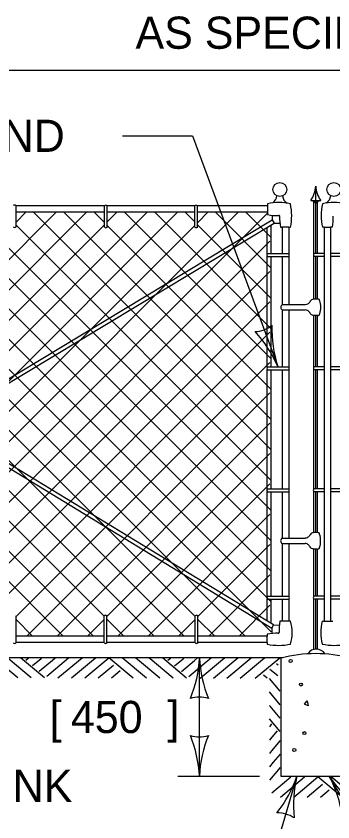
# Model space of a CAD drawing. Extents: x 49973.1 to 50021, y 49987.6 to 50015.4.
# Drawn here: x 49978.181 to 49978.772, y 50011.283 to 50012.786 of the extents above; entities that cross this region are included whole.
import ezdxf

# ---------------------------------------------------------------- set-up
doc = ezdxf.new("R2010")
doc.units = 0
for name, color, linetype in [('Level 1', 7, 'Continuous'), ('Level 2', 7, 'Continuous'), ('Level 3', 7, 'Continuous')]:
    doc.layers.add(name, color=color, linetype=linetype)

msp = doc.modelspace()

# ---------------------------------------------------------------- linework, layer by layer
at = {"layer": 'Level 1'}
for p, q in [((49978.7401, 50012.3432), (49978.7401, 50012.4689)), ((49978.6502, 50012.4358), (49978.6502, 50012.4319)), ((49978.7308, 50012.4423), (49978.7494, 50012.4423)), ((49978.7366, 50012.3431), (49978.7366, 50012.4399)), ((49978.7436, 50012.3432), (49978.7436, 50012.4396)), ((49977.5022, 50011.6663), (49978.256, 50012.4202)), ((49977.5222, 50011.6298), (49978.3126, 50012.4202)), ((49977.5348, 50012.4202), (49978.3255, 50011.6298)), ((49977.5914, 50012.4202), (49978.3451, 50011.6668)), ((49977.6718, 50011.6664), (49978.4256, 50012.4202)), ((49977.6918, 50011.6298), (49978.4822, 50012.4202)), ((49977.7044, 50012.4202), (49978.4946, 50011.6298)), ((49977.7609, 50012.4202), (49978.5149, 50011.6664)), ((49977.8416, 50011.6665), (49978.5954, 50012.4202)), ((49977.8742, 50012.4202), (49978.6567, 50011.638)), ((49977.9307, 50012.4202), (49978.6567, 50011.6939)), ((49978.044, 50012.4202), (49978.6567, 50011.8072)), ((49978.1004, 50012.4202), (49978.6567, 50011.8637)), ((49978.3456, 50012.4322), (49978.181, 50012.4322)), ((49978.1812, 50012.393), (49978.1812, 50012.4327)), ((49978.1812, 50012.402), (49978.1994, 50012.4202)), ((49978.3458, 50012.4202), (49978.1813, 50012.4202)), ((49978.2136, 50012.4202), (49978.6567, 50011.9769)), ((49978.2702, 50012.4202), (49978.6567, 50012.0335)), ((49978.3268, 50012.4202), (49978.3457, 50012.4013)), ((49978.3457, 50012.3925), (49978.3457, 50012.4322)), ((49978.5142, 50012.4322), (49978.351, 50012.4322)), ((49978.3512, 50012.3925), (49978.3512, 50012.4322)), ((49978.3512, 50012.4024), (49978.369, 50012.4202)), ((49978.5144, 50012.4202), (49978.3513, 50012.4202)), ((49978.3834, 50012.4202), (49978.6567, 50012.1467)), ((49978.4398, 50012.4202), (49978.6567, 50012.2031)), ((49978.4964, 50012.4202), (49978.5143, 50012.4024)), ((49978.5143, 50012.3927), (49978.5143, 50012.4324)), ((49978.5198, 50012.3927), (49978.5198, 50012.4324)), ((49978.65, 50012.4202), (49978.5198, 50012.4202)), ((49978.6502, 50012.4322), (49978.5199, 50012.4322)), ((49978.5199, 50012.4013), (49978.5388, 50012.4202)), ((49978.553, 50012.4202), (49978.6567, 50012.3163)), ((49978.6096, 50012.4202), (49978.6567, 50012.373)), ((49978.6502, 50012.4319), (49978.6502, 50012.4199)), ((49978.6502, 50012.4199), (49978.6502, 50012.416)), ((49977.3965, 50011.6456), (49978.6588, 50012.4061)), ((49978.6581, 50011.6442), (49977.4024, 50012.4082)), ((49978.6612, 50011.6505), (49977.4109, 50012.4113)), ((49977.8616, 50011.6298), (49978.6496, 50012.4178)), ((49978.6588, 50012.4147), (49978.6588, 50012.4061)), ((49978.6588, 50012.4061), (49978.6626, 50012.4002)), ((49977.4003, 50011.6397), (49978.6626, 50012.4002)), ((49977.5015, 50012.3969), (49978.269, 50011.6298)), ((49977.5786, 50011.6298), (49978.3457, 50012.3969)), ((49977.6718, 50012.3965), (49978.4388, 50011.6298)), ((49977.7484, 50011.6298), (49978.5143, 50012.3957)), ((49977.8416, 50012.3962), (49978.6083, 50011.6298)), ((49978.0112, 50012.3963), (49978.6567, 50011.7508)), ((49978.1812, 50012.396), (49978.6567, 50011.9202)), ((49978.3512, 50012.3958), (49978.6567, 50012.09)), ((49978.5198, 50012.3968), (49978.6567, 50012.2596)), ((49978.6497, 50012.3429), (49978.6497, 50012.3925)), ((49978.6567, 50012.3432), (49978.6567, 50012.3967)), ((49978.6626, 50012.4002), (49978.6733, 50012.4)), ((49978.6745, 50012.3923), (49978.6778, 50012.3923)), ((49978.6898, 50012.3923), (49978.6778, 50012.3923)), ((49978.6778, 50012.3923), (49978.6778, 50012.3432)), ((49978.6898, 50012.3923), (49978.693, 50012.3923)), ((49978.6898, 50012.3923), (49978.6898, 50012.3431)), ((49978.7557, 50012.3923), (49978.7525, 50012.3923)), ((49978.7557, 50012.3923), (49978.7677, 50012.3923)), ((49978.7557, 50012.3923), (49978.7557, 50012.3429)), ((49978.771, 50012.3923), (49978.7677, 50012.3923)), ((49978.7677, 50012.3923), (49978.7677, 50012.3432)), ((49977.918, 50011.6298), (49978.6544, 50012.3662)), ((49978.65, 50012.3432), (49978.6897, 50012.3432)), ((49978.7557, 50012.3432), (49978.7368, 50012.3432)), ((49978.7677, 50012.3432), (49978.7677, 50012.1318)), ((49978.7956, 50012.3432), (49978.7677, 50012.3432)), ((49978.6497, 50012.1314), (49978.6497, 50012.3381)), ((49978.65, 50012.3377), (49978.6897, 50012.3377)), ((49978.6567, 50012.1319), (49978.6567, 50012.3377)), ((49978.6778, 50012.3377), (49978.6778, 50012.248)), ((49978.6898, 50012.3379), (49978.6898, 50012.248)), ((49978.7366, 50012.2584), (49978.7366, 50012.338)), ((49978.7557, 50012.3377), (49978.7367, 50012.3377)), ((49978.7401, 50012.2584), (49978.7401, 50012.3377)), ((49978.7436, 50012.2584), (49978.7436, 50012.3377)), ((49978.7557, 50012.3429), (49978.7557, 50012.1319)), ((49978.7955, 50012.3377), (49978.7677, 50012.3377)), ((49978.0112, 50011.6665), (49978.6544, 50012.3096)), ((49978.0312, 50011.6298), (49978.6544, 50012.253)), ((49978.7436, 50012.2584), (49978.7367, 50012.2584)), ((49978.6778, 50012.248), (49978.7206, 50012.248)), ((49978.6778, 50012.238), (49978.7206, 50012.238)), ((49978.6778, 50012.238), (49978.6778, 50012.1319)), ((49978.6898, 50012.238), (49978.6898, 50012.1319)), ((49978.7366, 50012.1318), (49978.7366, 50012.2276)), ((49978.7438, 50012.2276), (49978.7367, 50012.2276)), ((49978.7401, 50012.1319), (49978.7401, 50012.2276)), ((49978.7436, 50012.1319), (49978.7436, 50012.2276)), ((49978.0878, 50011.6298), (49978.6544, 50012.1964)), ((49978.181, 50011.6664), (49978.6544, 50012.1398)), ((49978.6497, 50011.9041), (49978.6497, 50012.1269)), ((49978.6501, 50012.1264), (49978.6898, 50012.1264)), ((49978.6502, 50012.1319), (49978.6898, 50012.1319)), ((49978.6567, 50011.9044), (49978.6567, 50012.1264)), ((49978.6778, 50012.1264), (49978.6778, 50011.9044)), ((49978.6898, 50012.1264), (49978.6898, 50011.9043)), ((49978.7366, 50011.9044), (49978.7366, 50012.1266)), ((49978.7557, 50012.1264), (49978.7367, 50012.1264)), ((49978.7557, 50012.1319), (49978.7368, 50012.1319)), ((49978.7401, 50011.9044), (49978.7401, 50012.1264)), ((49978.7436, 50011.9044), (49978.7436, 50012.1264)), ((49978.7557, 50012.1319), (49978.7557, 50011.904)), ((49978.7954, 50012.1319), (49978.7677, 50012.1319)), ((49978.7677, 50012.1318), (49978.7677, 50011.8988)), ((49978.7954, 50012.1264), (49978.7677, 50012.1264)), ((49978.201, 50011.6298), (49978.6544, 50012.0832)), ((49978.2576, 50011.6298), (49978.6544, 50012.0266)), ((49978.3506, 50011.6664), (49978.6544, 50011.9702)), ((49978.3706, 50011.6298), (49978.6544, 50011.9136)), ((49978.6497, 50011.7034), (49978.6497, 50011.8993)), ((49978.65, 50011.9044), (49978.6897, 50011.9044)), ((49978.65, 50011.8989), (49978.6897, 50011.8989)), ((49978.6567, 50011.704), (49978.6567, 50011.8989)), ((49978.6778, 50011.8989), (49978.6778, 50011.8124)), ((49978.6898, 50011.8991), (49978.6898, 50011.8124)), ((49978.7557, 50011.8989), (49978.7365, 50011.8989)), ((49978.7557, 50011.9044), (49978.7366, 50011.9044)), ((49978.7366, 50011.8228), (49978.7366, 50011.8989)), ((49978.7401, 50011.8228), (49978.7401, 50011.8989)), ((49978.7436, 50011.8229), (49978.7436, 50011.8989)), ((49978.7557, 50011.904), (49978.7557, 50011.7039)), ((49978.7956, 50011.9044), (49978.7677, 50011.9044)), ((49978.7955, 50011.8989), (49978.7677, 50011.8989)), ((49978.7677, 50011.8988), (49978.7677, 50011.704)), ((49978.4272, 50011.6298), (49978.6544, 50011.857)), ((49978.7433, 50011.8228), (49978.7364, 50011.8228)), ((49978.6775, 50011.8024), (49978.7203, 50011.8024)), ((49978.6776, 50011.8124), (49978.7203, 50011.8124)), ((49978.6778, 50011.8024), (49978.6778, 50011.704)), ((49978.6898, 50011.8024), (49978.6898, 50011.704)), ((49978.5204, 50011.6663), (49978.6544, 50011.8004)), ((49978.7435, 50011.792), (49978.7364, 50011.792)), ((49978.7366, 50011.704), (49978.7366, 50011.792)), ((49978.7401, 50011.704), (49978.7401, 50011.792)), ((49978.7436, 50011.704), (49978.7436, 50011.792)), ((49978.5404, 50011.6298), (49978.6544, 50011.7438)), ((49978.6497, 50011.6575), (49978.6497, 50011.6992)), ((49978.6502, 50011.704), (49978.6899, 50011.704)), ((49978.6502, 50011.6985), (49978.6899, 50011.6985)), ((49978.6567, 50011.6533), (49978.6567, 50011.6985)), ((49978.6778, 50011.6985), (49978.6778, 50011.6574)), ((49978.6898, 50011.6985), (49978.6898, 50011.6574)), ((49978.7557, 50011.6985), (49978.7365, 50011.6985)), ((49978.7557, 50011.704), (49978.7366, 50011.704)), ((49978.7366, 50011.6051), (49978.7366, 50011.6985)), ((49978.7401, 50011.6056), (49978.7401, 50011.6985)), ((49978.7436, 50011.6055), (49978.7436, 50011.6985)), ((49978.7557, 50011.7039), (49978.7557, 50011.6574)), ((49978.7677, 50011.704), (49978.7677, 50011.6574)), ((49978.7953, 50011.704), (49978.7677, 50011.704)), ((49978.7953, 50011.6985), (49978.7677, 50011.6985)), ((49978.597, 50011.6298), (49978.6544, 50011.6872)), ((49978.181, 50011.6173), (49978.181, 50011.6675)), ((49978.3451, 50011.6173), (49978.3451, 50011.6675)), ((49978.3506, 50011.6173), (49978.3506, 50011.6675)), ((49978.5149, 50011.6173), (49978.5149, 50011.6675)), ((49978.5204, 50011.6173), (49978.5204, 50011.6675)), ((49978.181, 50011.6607), (49978.2119, 50011.6298)), ((49978.314, 50011.6298), (49978.3451, 50011.6609)), ((49978.3506, 50011.6612), (49978.3821, 50011.6298)), ((49978.4838, 50011.6298), (49978.5149, 50011.6608)), ((49978.5204, 50011.6609), (49978.5516, 50011.6298)), ((49978.6773, 50011.6574), (49978.6734, 50011.6574)), ((49978.6893, 50011.6574), (49978.6773, 50011.6574)), ((49978.6932, 50011.6574), (49978.6893, 50011.6574)), ((49978.7523, 50011.6574), (49978.7562, 50011.6574)), ((49978.7562, 50011.6574), (49978.7682, 50011.6574)), ((49978.7682, 50011.6574), (49978.7721, 50011.6574)), ((49978.6581, 50011.6442), (49978.6612, 50011.6505)), ((49978.6581, 50011.6442), (49978.6581, 50011.6344)), ((49978.6612, 50011.6505), (49978.6723, 50011.6503)), ((49978.3451, 50011.6298), (49978.181, 50011.6298)), ((49978.5149, 50011.6298), (49978.3506, 50011.6298)), ((49978.6497, 50011.6298), (49978.5204, 50011.6298)), ((49978.6497, 50011.6331), (49978.6497, 50011.6298)), ((49978.6497, 50011.6178), (49978.6497, 50011.6298)), ((49978.3451, 50011.6178), (49978.181, 50011.6178)), ((49978.5149, 50011.6178), (49978.3506, 50011.6178)), ((49978.6497, 50011.6178), (49978.5204, 50011.6178)), ((49978.6497, 50011.6178), (49978.6497, 50011.6146)), ((49978.6782, 50011.5893), (49977.3829, 50011.5893)), ((49978.1841, 50011.5516), (49978.1394, 50011.5892)), ((49978.2091, 50011.5516), (49978.1661, 50011.5877)), ((49978.2341, 50011.5516), (49978.1894, 50011.5892)), ((49978.1991, 50011.5851), (49978.2041, 50011.5893)), ((49978.2118, 50011.5749), (49978.2275, 50011.588)), ((49978.2243, 50011.5644), (49978.2489, 50011.585)), ((49978.2275, 50011.588), (49978.229, 50011.5892)), ((49978.2382, 50011.555), (49978.2705, 50011.5821)), ((49978.2489, 50011.585), (49978.254, 50011.5892)), ((49978.2591, 50011.5516), (49978.3041, 50011.5892)), ((49978.2705, 50011.5821), (49978.2791, 50011.5892)), ((49978.2841, 50011.5516), (49978.3291, 50011.5892)), ((49978.3091, 50011.5516), (49978.3539, 50011.5892)), ((49978.3992, 50011.5511), (49978.3539, 50011.5892)), ((49978.4242, 50011.5511), (49978.3789, 50011.5892)), ((49978.4492, 50011.5511), (49978.4039, 50011.5892)), ((49978.4312, 50011.5872), (49978.4289, 50011.5892)), ((49978.4742, 50011.5511), (49978.4312, 50011.5872)), ((49978.4992, 50011.5511), (49978.4539, 50011.5892)), ((49978.4642, 50011.5846), (49978.4692, 50011.5888)), ((49978.4692, 50011.5888), (49978.4697, 50011.5892)), ((49978.4769, 50011.5744), (49978.4926, 50011.5875)), ((49978.4894, 50011.5639), (49978.514, 50011.5845)), ((49978.4926, 50011.5875), (49978.4947, 50011.5892)), ((49978.5033, 50011.5545), (49978.5356, 50011.5816)), ((49978.514, 50011.5845), (49978.5197, 50011.5892)), ((49978.5242, 50011.5511), (49978.5697, 50011.5892)), ((49978.5356, 50011.5816), (49978.5448, 50011.5892)), ((49978.5492, 50011.5511), (49978.5947, 50011.5892)), ((49978.5742, 50011.5511), (49978.6196, 50011.5892)), ((49978.5992, 50011.5511), (49978.6447, 50011.5892)), ((49978.6274, 50011.5512), (49978.6729, 50011.5893)), ((49978.6703, 50011.5754), (49978.6668, 50011.5783)), ((49978.6751, 50011.5885), (49978.6751, 50011.3684)), ((49978.3341, 50011.5516), (49978.3625, 50011.5754)), ((49978.3591, 50011.5516), (49978.3754, 50011.5653)), ((49978.6691, 50011.5554), (49978.6547, 50011.5674)), ((49978.6492, 50011.5511), (49978.6424, 50011.5568)), ((49978.6736, 50011.5268), (49978.6537, 50011.5505)), ((49978.6736, 50011.5018), (49978.6537, 50011.5255)), ((49978.6552, 50011.4988), (49978.6537, 50011.5005)), ((49978.6736, 50011.4768), (49978.6552, 50011.4988)), ((49978.6736, 50011.4518), (49978.6537, 50011.4755)), ((49978.6578, 50011.4658), (49978.6536, 50011.4608)), ((49978.668, 50011.4531), (49978.6549, 50011.4374)), ((49978.6549, 50011.4374), (49978.6537, 50011.4359)), ((49978.6736, 50011.4347), (49978.6579, 50011.416)), ((49978.6579, 50011.416), (49978.6537, 50011.4109)), ((49978.6736, 50011.4096), (49978.6608, 50011.3944)), ((49978.6608, 50011.3944), (49978.6537, 50011.3858)), ((49978.6736, 50011.3846), (49978.6537, 50011.3608)), ((49978.6583, 50011.3375), (49978.6939, 50011.3672)), ((49978.6742, 50011.3296), (49978.7192, 50011.3672)), ((49978.6751, 50011.3684), (49978.8051, 50011.3684)), ((49978.6992, 50011.3296), (49978.744, 50011.3672)), ((49978.7893, 50011.3291), (49978.744, 50011.3672)), ((49978.8143, 50011.3291), (49978.769, 50011.3672)), ((49978.7242, 50011.3296), (49978.7526, 50011.3534)), ((49978.7492, 50011.3296), (49978.7655, 50011.3433))]:
    msp.add_line(p, q, dxfattribs=at)
msp.add_lwpolyline([(49978.7191, 50011.503), (49978.7239, 50011.5092), (49978.7259, 50011.4996)], close=True, dxfattribs=at)
for centre, radius in [((49978.6731, 50012.4626), 0.013), ((49978.7738, 50012.4628), 0.013), ((49978.6933, 50011.5832), 0.00279), ((49978.7125, 50011.5393), 0.00279), ((49978.7191, 50011.4488), 0.00279), ((49978.7001, 50011.4172), 0.00279)]:
    msp.add_circle(centre, radius, dxfattribs=at)
for centre, radius, start, end in [((49978.689, 50012.4718), 0.0512, 324.8085, 356.9846), ((49978.7912, 50012.4718), 0.0512, 183.0162, 215.3127), ((49978.6482, 50012.4537), 0.0197, 306.5272, 351.7381), ((49978.6975, 50012.4537), 0.0197, 188.9769, 236.2764), ((49978.7489, 50012.4539), 0.0197, 303.324, 351.7381), ((49978.1785, 50012.4295), 0.00424, 49.8072, 130.5105), ((49978.3485, 50012.429), 0.00424, 49.8072, 130.5105), ((49978.5171, 50012.4292), 0.00424, 49.8072, 130.5105), ((49978.6715, 50012.3564), 0.0823, 74.999, 105.0029), ((49978.5924, 50012.4136), 0.1029, 348.0613, 12.47), ((49978.7268, 50012.4247), 0.0181, 41.6769, 77.2182), ((49978.7538, 50012.4247), 0.0181, 103.984, 138.3231), ((49978.8532, 50012.4136), 0.1029, 167.5295, 191.9387), ((49978.774, 50012.3564), 0.0823, 74.9971, 104.9997), ((49978.6682, 50012.503), 0.0888, 258.3626, 272.1883), ((49978.6719, 50012.4134), 0.000958, 349.4816, 109.6717), ((49978.765, 50012.4104), 0.0923, 178.2536, 191.2832), ((49978.6806, 50012.4104), 0.0923, 348.7168, 1.7464), ((49978.1785, 50012.396), 0.00408, 227.6835, 312.675), ((49978.3485, 50012.3955), 0.00408, 227.6835, 312.675), ((49978.5171, 50012.3957), 0.00408, 227.6835, 312.675), ((49978.653, 50012.3405), 0.00408, 137.981, 222.675), ((49978.6865, 50012.3405), 0.00424, 319.8072, 40.7421), ((49978.74, 50012.3405), 0.00424, 139.2579, 220.1928), ((49978.7089, 50012.243), 0.0406, 342.3574, 17.6491), ((49978.6805, 50012.243), 0.00567, 118.1722, 241.7896), ((49978.653, 50012.1292), 0.00393, 135.1005, 223.8252), ((49978.6866, 50012.1292), 0.00424, 319.8072, 40.7421), ((49978.74, 50012.1292), 0.00424, 139.2579, 220.1928), ((49978.653, 50011.9017), 0.00408, 137.981, 222.675), ((49978.6865, 50011.9017), 0.00424, 319.8072, 40.7421), ((49978.7398, 50011.9017), 0.00424, 139.2579, 220.1928), ((49978.7086, 50011.8074), 0.0406, 342.3574, 17.6491), ((49978.6802, 50011.8074), 0.00567, 118.0389, 241.7896), ((49978.6532, 50011.7013), 0.00408, 137.6835, 222.675), ((49978.6867, 50011.7013), 0.00424, 319.8072, 40.7421), ((49978.7398, 50011.7013), 0.00424, 139.2579, 220.1928), ((49978.3479, 50011.6643), 0.00424, 49.4895, 130.1928), ((49978.5177, 50011.6643), 0.00424, 49.4895, 130.1928), ((49978.7604, 50011.6395), 0.0888, 168.3626, 182.0358), ((49978.6138, 50011.6361), 0.0823, 344.999, 15.0029), ((49978.8318, 50011.6361), 0.0823, 164.9971, 195.001), ((49978.6678, 50011.5427), 0.0923, 88.5988, 101.2832), ((49978.6697, 50011.6369), 0.00206, 280.2386, 344.6517), ((49978.1783, 50011.6203), 0.00408, 227.325, 312.3165), ((49978.3479, 50011.6203), 0.00408, 227.325, 312.3165), ((49978.5177, 50011.6203), 0.00408, 227.325, 312.3165), ((49978.671, 50011.7153), 0.1029, 258.0613, 282.47), ((49978.7746, 50011.7153), 0.1029, 257.53, 281.9387), ((49978.7401, 50011.3472), 0.2499, 74.9261, 105.0737), ((49978.7413, 50011.5869), 0.0187, 30.8214, 148.6079)]:
    msp.add_arc(centre, radius, start, end, dxfattribs=at)
for points in [[(49978.7367, 50012.2584), (49978.7341, 50012.2578), (49978.7311, 50012.256), (49978.729, 50012.2527), (49978.727, 50012.2506), (49978.7245, 50012.2488), (49978.7206, 50012.2479)], [(49978.7475, 50012.2553), (49978.7473, 50012.2566), (49978.7467, 50012.2577), (49978.7456, 50012.2582), (49978.7436, 50012.2584)], [(49978.7367, 50012.2276), (49978.7341, 50012.2282), (49978.7311, 50012.23), (49978.729, 50012.2333), (49978.727, 50012.2354), (49978.7245, 50012.2372), (49978.7206, 50012.238)], [(49978.7438, 50012.2276), (49978.7453, 50012.2279), (49978.7467, 50012.2286), (49978.7475, 50012.2307)], [(49978.7364, 50011.8228), (49978.7338, 50011.8222), (49978.7308, 50011.8204), (49978.7287, 50011.8171), (49978.7267, 50011.815), (49978.7242, 50011.8132), (49978.7203, 50011.8123)], [(49978.7472, 50011.8197), (49978.747, 50011.821), (49978.7464, 50011.8221), (49978.7453, 50011.8226), (49978.7433, 50011.8228)], [(49978.7364, 50011.792), (49978.7338, 50011.7926), (49978.7308, 50011.7944), (49978.7287, 50011.7977), (49978.7267, 50011.7998), (49978.7242, 50011.8016), (49978.7203, 50011.8024)], [(49978.7435, 50011.792), (49978.745, 50011.7923), (49978.7464, 50011.793), (49978.7472, 50011.7951)]]:
    msp.add_spline(points, degree=3, dxfattribs=at)
at = {"layer": 'Level 3'}
for p, q in [((49977.3379, 50012.6852), (49980.1076, 50012.6852)), ((49978.3797, 50012.5629), (49978.5101, 50012.5629)), ((49978.5101, 50012.5629), (49978.6694, 50012.1323)), ((49978.523, 50011.3684), (49978.523, 50011.5893)), ((49978.523, 50011.5406), (49978.523, 50011.5854)), ((49978.483, 50011.3684), (49978.6351, 50011.3684)), ((49978.7049, 50011.3684), (49978.607, 50011.0349)), ((49978.8402, 50011.2425), (49978.7655, 50011.3684))]:
    msp.add_line(p, q, dxfattribs=at)
for centre, radius, start, end in [((49978.6244, 50012.2524), 0.0548, 272.7096, 308.432), ((49978.8806, 50012.2018), 0.2223, 178.0268, 198.2103), ((49978.4556, 50012.0398), 0.233, 23.3981, 42.648), ((49978.3009, 50011.5985), 0.2223, 337.456, 357.6395), ((49978.7558, 50011.6008), 0.233, 182.8273, 202.0772), ((49978.523, 50011.4611), 0.0548, 72.1388, 107.8612), ((49978.523, 50011.4966), 0.0548, 252.1388, 287.8612), ((49978.2903, 50011.3569), 0.233, 2.8273, 22.0772), ((49978.7452, 50011.3593), 0.2223, 157.456, 177.6395), ((49978.4943, 50011.4394), 0.2223, 321.1983, 341.3818), ((49978.9316, 50011.3143), 0.233, 166.5696, 185.8195), ((49978.5692, 50011.2642), 0.2223, 7.7836, 27.9671), ((49978.9606, 50011.4959), 0.233, 213.1549, 232.4047), ((49978.669, 50011.2453), 0.0548, 55.8811, 91.6035)]:
    msp.add_arc(centre, radius, start, end, dxfattribs=at)

# ---------------------------------------------------------------- texts
at = {"layer": 'Level 2'}
for s, p in [('AS SPECIFIED', (49978.4038, 50012.7252)), ('FABRIC BAND', (49977.7324, 50012.5329)), ('[', (49978.2435, 50011.4489)), ('450', (49978.2832, 50011.4489)), (']', (49978.4632, 50011.4489)), ('CHAIN LINK', (49977.8357, 50011.3203))]:
    msp.add_text(s, height=0.06, dxfattribs=at).set_placement(p)

doc.saveas('drawing.dxf')
